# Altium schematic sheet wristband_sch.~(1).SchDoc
size A2
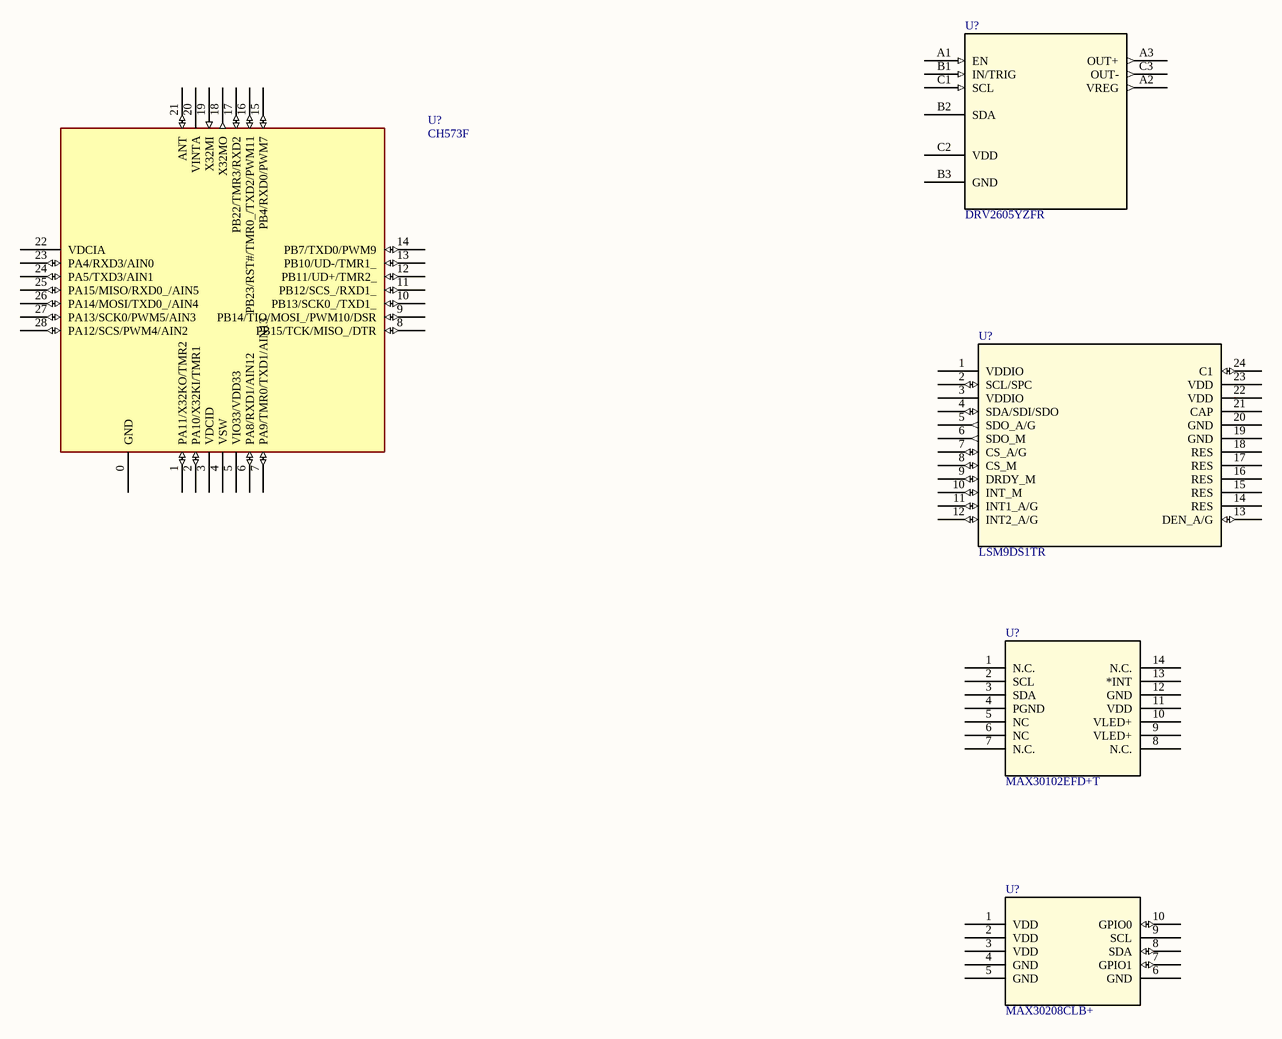
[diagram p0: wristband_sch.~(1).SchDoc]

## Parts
(Parts that share a designator on the sheet are numbered #1, #2 ... from top to bottom, then left to right.)
U?#1  DRV2605YZFR  [YZF9]
U?#2  CH573F  [QFN28_4X4]
U?#3  LSM9DS1TR  [LGA-24_3X3P5X1_STM]
U?#4  MAX30102EFD+T  [21-1048_F143A5+1_MXM]
U?#5  MAX30208CLB+  [21-100265_MXM]

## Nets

Not connected (* = marked no-connect by the designer): U?#1 A1(EN) A2(VREG) A3(OUT+) B1(IN/TRIG) B2(SDA) B3(GND) C1(SCL) C2(VDD) C3(OUT-); U?#2 0(GND) 1(PA11/X32KO/TMR2) 2(PA10/X32KI/TMR1) 3(VDCID) 4(VSW) 5(VIO33/VDD33) 6(PA8/RXD1/AIN12) 7(PA9/TMR0/TXD1/AIN13) 8(PB15/TCK/MISO_/DTR) 9(PB14/TIO/MOSI_/PWM10/DSR) 10(PB13/SCK0_/TXD1_) 11(PB12/SCS_/RXD1_) 12(PB11/UD+/TMR2_) 13(PB10/UD-/TMR1_) 14(PB7/TXD0/PWM9) 15(PB4/RXD0/PWM7) 16(PB23/RST#/TMR0_/TXD2/PWM11) 17(PB22/TMR3/RXD2) 18(X32MO) 19(X32MI) 20(VINTA) 21(ANT) 22(VDCIA) 23(PA4/RXD3/AIN0) 24(PA5/TXD3/AIN1) 25(PA15/MISO/RXD0_/AIN5) 26(PA14/MOSI/TXD0_/AIN4) 27(PA13/SCK0/PWM5/AIN3) 28(PA12/SCS/PWM4/AIN2); U?#3 1(VDDIO) 2(SCL/SPC) 3(VDDIO) 4(SDA/SDI/SDO) 5(SDO_A/G) 6(SDO_M) 7(CS_A/G) 8(CS_M) 9(DRDY_M) 10(INT_M) 11(INT1_A/G) 12(INT2_A/G) 13(DEN_A/G) 14(RES) 15(RES) 16(RES) 17(RES) 18(RES) 19(GND) 20(GND) 21(CAP) 22(VDD) 23(VDD) 24(C1); U?#4 1(N.C.) 2(SCL) 3(SDA) 4(PGND) 5(NC) 6(NC) 7(N.C.) 8(N.C.) 9(VLED+) 10(VLED+) 11(VDD) 12(GND) 13(*INT) 14(N.C.); U?#5 1(VDD) 2(VDD) 3(VDD) 4(GND) 5(GND) 6(GND) 7(GPIO1) 8(SDA) 9(SCL) 10(GPIO0)

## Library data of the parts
U?#1 = DRV2605YZFR: No Description Available; Vendor: TEXAS INSTRUMENTS
U?#2 = CH573F: RISC-V MCU with BLE/USB/ADC/SPI/4*UART
U?#3 = LSM9DS1TR: No Description Available; Vendor: STMicroelectronics; Built_By: EMA_Jessica; SourceLibrary: Updates_to_database_2020-11-03
U?#4 = MAX30102EFD+T: No Description Available; SourceLibrary: Update_to_database_2021-01-29; Built_By: EMA_UL_Team; Vendor: Maxim Integrated Products
U?#5 = MAX30208CLB+: No Description Available; Vendor: Maxim Integrated Products; Built_By: EMA_Rebekah; SourceLibrary: Maxim_2019-09-13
